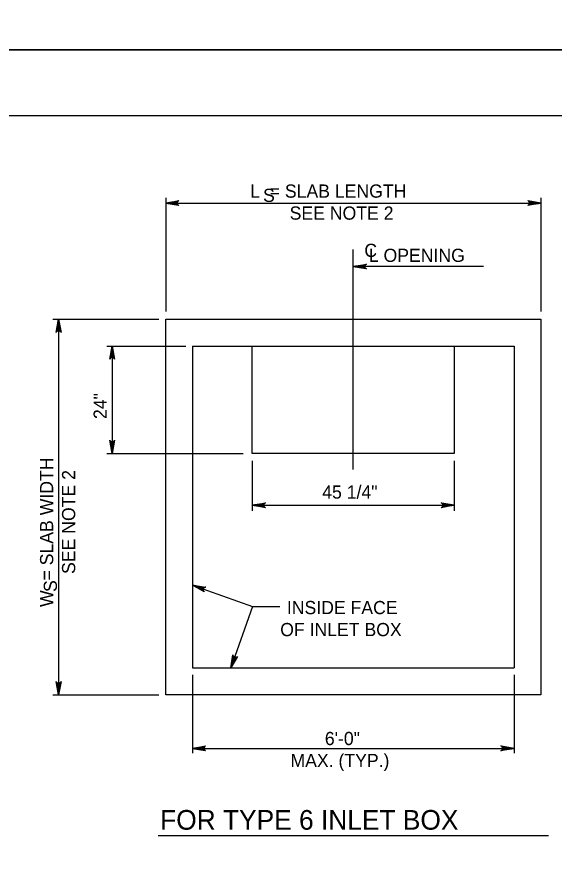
# Model space of a CAD drawing. Extents: x -6420 to 49575, y -4552 to 11624.
# Drawn here: x -5351 to -4949, y 9073 to 9700 of the extents above; entities that cross this region are included whole.
import ezdxf

# ---------------------------------------------------------------- set-up
doc = ezdxf.new("R2010")
doc.units = 0
doc.layers.add('1', color=7, linetype='Continuous')
doc.layers.add('PLT-BNDY', color=7, linetype='Continuous')

msp = doc.modelspace()

# ---------------------------------------------------------------- linework, layer by layer
at = {"layer": '1'}
for p, q in [((-5239.43, 9564.78), (-5239.43, 9479.86)), ((-4959.43, 9564.78), (-4959.43, 9479.86)), ((-5239.43, 9560.79), (-4959.43, 9560.79)), ((-5099.43, 9362.17), (-5099.43, 9526.19)), ((-5002.34, 9513.5), (-5099.43, 9513.5)), ((-5323.67, 9474.12), (-5244.69, 9474.12)), ((-5319.43, 9474.12), (-5319.43, 9194.12)), ((-5283.43, 9454.12), (-5224.45, 9454.12)), ((-5279.43, 9454.12), (-5279.43, 9374.12)), ((-5219.43, 9454.12), (-5219.43, 9214.12)), ((-5219.43, 9454.12), (-4979.43, 9454.12)), ((-5174.84, 9454.12), (-5024.01, 9454.12)), ((-5174.84, 9374.12), (-5174.84, 9454.12)), ((-5024.01, 9454.12), (-5024.01, 9374.12)), ((-4979.43, 9454.12), (-4979.43, 9214.12)), ((-5283.43, 9374.12), (-5181.53, 9374.12)), ((-5024.01, 9374.12), (-5174.84, 9374.12)), ((-5174.84, 9368.54), (-5174.84, 9331.24)), ((-5024.01, 9368.54), (-5024.01, 9331.24)), ((-5174.84, 9335.45), (-5024.01, 9335.45)), ((-5219.43, 9275.87), (-5174.71, 9259.98)), ((-5174.71, 9259.98), (-5190.87, 9214.12)), ((-5174.71, 9259.98), (-5154.27, 9259.98)), ((-5219.43, 9214.12), (-4979.43, 9214.12)), ((-5219.43, 9209), (-5219.43, 9150.51)), ((-4979.43, 9209), (-4979.43, 9150.51)), ((-5323.67, 9194.12), (-5244.69, 9194.12)), ((-5219.43, 9154.12), (-4979.43, 9154.12)), ((-5245.19, 9089.22), (-4953.81, 9089.22))]:
    msp.add_line(p, q, dxfattribs=at)
for points in [[(-3713.67, 7775.47), (-3713.67, 9625.87), (-6292.41, 9625.87), (-6292.41, 7775.47), (-3713.67, 7775.47), (-3713.67, 7861.95), (-4369.84, 7861.95), (-4369.84, 8074.15), (-3713.67, 8074.15), (-3713.67, 8169.17), (-4369.84, 8169.17), (-4369.84, 7775.47), (-4111.31, 7775.47), (-4111.31, 7861.95), (-4111.31, 7775.47), (-3858.68, 7775.47), (-3858.68, 7861.95), (-3858.68, 7821.54), (-3713.67, 7821.54)], [(-5239.43, 9560.79), (-5229.64, 9562.63), (-5230.02, 9562.37), (-5230.4, 9562.1), (-5230.59, 9561.78), (-5230.78, 9561.45), (-5230.84, 9561.12), (-5230.9, 9560.79), (-5230.84, 9560.46), (-5230.78, 9560.14), (-5230.59, 9559.81), (-5230.4, 9559.48), (-5230.02, 9559.22), (-5229.64, 9558.96), (-5239.43, 9560.79), (-5230.02, 9559.22), (-5230.4, 9559.48), (-5239.43, 9560.79), (-5230.59, 9559.81), (-5230.78, 9560.14), (-5239.43, 9560.79), (-5230.84, 9560.46), (-5230.9, 9560.79), (-5239.43, 9560.79), (-5230.84, 9561.12), (-5230.78, 9561.45), (-5239.43, 9560.79), (-5230.59, 9561.78), (-5230.4, 9562.1), (-5239.43, 9560.79), (-5230.02, 9562.37)], [(-4959.43, 9560.79), (-4969.21, 9558.96), (-4968.84, 9559.22), (-4968.46, 9559.48), (-4968.26, 9559.81), (-4968.07, 9560.14), (-4968.01, 9560.46), (-4967.96, 9560.79), (-4968.01, 9561.12), (-4968.07, 9561.45), (-4968.26, 9561.78), (-4968.46, 9562.1), (-4968.84, 9562.37), (-4969.21, 9562.63), (-4959.43, 9560.79), (-4968.84, 9562.37), (-4968.46, 9562.1), (-4959.43, 9560.79), (-4968.26, 9561.78), (-4968.07, 9561.45), (-4959.43, 9560.79), (-4968.01, 9561.12), (-4967.96, 9560.79), (-4959.43, 9560.79), (-4968.01, 9560.46), (-4968.07, 9560.14), (-4959.43, 9560.79), (-4968.26, 9559.81), (-4968.46, 9559.48), (-4959.43, 9560.79), (-4968.84, 9559.22)], [(-5099.43, 9513.5), (-5089.64, 9515.33), (-5090.02, 9515.07), (-5090.4, 9514.81), (-5090.59, 9514.48), (-5090.78, 9514.16), (-5090.84, 9513.83), (-5090.9, 9513.5), (-5090.84, 9513.17), (-5090.78, 9512.84), (-5090.59, 9512.52), (-5090.4, 9512.19), (-5090.02, 9511.93), (-5089.64, 9511.66), (-5099.43, 9513.5), (-5090.02, 9511.93), (-5090.4, 9512.19), (-5099.43, 9513.5), (-5090.59, 9512.52), (-5090.78, 9512.84), (-5099.43, 9513.5), (-5090.84, 9513.17), (-5090.9, 9513.5), (-5099.43, 9513.5), (-5090.84, 9513.83), (-5090.78, 9514.16), (-5099.43, 9513.5), (-5090.59, 9514.48), (-5090.4, 9514.81), (-5099.43, 9513.5), (-5090.02, 9515.07)], [(-5319.43, 9474.12), (-5317.59, 9464.34), (-5317.85, 9464.72), (-5318.12, 9465.09), (-5318.44, 9465.29), (-5318.77, 9465.48), (-5319.1, 9465.54), (-5319.43, 9465.59), (-5319.76, 9465.54), (-5320.08, 9465.48), (-5320.41, 9465.29), (-5320.74, 9465.09), (-5321, 9464.72), (-5321.26, 9464.34), (-5319.43, 9474.12), (-5321, 9464.72), (-5320.74, 9465.09), (-5319.43, 9474.12), (-5320.41, 9465.29), (-5320.08, 9465.48), (-5319.43, 9474.12), (-5319.76, 9465.54), (-5319.43, 9465.59), (-5319.43, 9474.12), (-5319.1, 9465.54), (-5318.77, 9465.48), (-5319.43, 9474.12), (-5318.44, 9465.29), (-5318.12, 9465.09), (-5319.43, 9474.12), (-5317.85, 9464.72)], [(-5279.43, 9454.12), (-5277.59, 9444.34), (-5277.85, 9444.72), (-5278.12, 9445.09), (-5278.44, 9445.29), (-5278.77, 9445.48), (-5279.1, 9445.54), (-5279.43, 9445.59), (-5279.76, 9445.54), (-5280.08, 9445.48), (-5280.41, 9445.29), (-5280.74, 9445.09), (-5281, 9444.72), (-5281.26, 9444.34), (-5279.43, 9454.12), (-5281, 9444.72), (-5280.74, 9445.09), (-5279.43, 9454.12), (-5280.41, 9445.29), (-5280.08, 9445.48), (-5279.43, 9454.12), (-5279.76, 9445.54), (-5279.43, 9445.59), (-5279.43, 9454.12), (-5279.1, 9445.54), (-5278.77, 9445.48), (-5279.43, 9454.12), (-5278.44, 9445.29), (-5278.12, 9445.09), (-5279.43, 9454.12), (-5277.85, 9444.72)], [(-5279.43, 9374.12), (-5281.26, 9383.91), (-5281, 9383.53), (-5280.74, 9383.16), (-5280.41, 9382.96), (-5280.08, 9382.77), (-5279.76, 9382.71), (-5279.43, 9382.65), (-5279.1, 9382.71), (-5278.77, 9382.77), (-5278.44, 9382.96), (-5278.12, 9383.16), (-5277.85, 9383.53), (-5277.59, 9383.91), (-5279.43, 9374.12), (-5277.85, 9383.53), (-5278.12, 9383.16), (-5279.43, 9374.12), (-5278.44, 9382.96), (-5278.77, 9382.77), (-5279.43, 9374.12), (-5279.1, 9382.71), (-5279.43, 9382.65), (-5279.43, 9374.12), (-5279.76, 9382.71), (-5280.08, 9382.77), (-5279.43, 9374.12), (-5280.41, 9382.96), (-5280.74, 9383.16), (-5279.43, 9374.12), (-5281, 9383.53)], [(-5174.84, 9335.45), (-5165.06, 9337.28), (-5165.44, 9337.02), (-5165.81, 9336.76), (-5166.01, 9336.43), (-5166.2, 9336.1), (-5166.26, 9335.78), (-5166.31, 9335.45), (-5166.26, 9335.12), (-5166.2, 9334.79), (-5166.01, 9334.46), (-5165.81, 9334.14), (-5165.44, 9333.87), (-5165.06, 9333.61), (-5174.84, 9335.45), (-5165.44, 9333.87), (-5165.81, 9334.14), (-5174.84, 9335.45), (-5166.01, 9334.46), (-5166.2, 9334.79), (-5174.84, 9335.45), (-5166.26, 9335.12), (-5166.31, 9335.45), (-5174.84, 9335.45), (-5166.26, 9335.78), (-5166.2, 9336.1), (-5174.84, 9335.45), (-5166.01, 9336.43), (-5165.81, 9336.76), (-5174.84, 9335.45), (-5165.44, 9337.02)], [(-5024.01, 9335.45), (-5033.8, 9333.61), (-5033.42, 9333.87), (-5033.04, 9334.14), (-5032.85, 9334.46), (-5032.65, 9334.79), (-5032.6, 9335.12), (-5032.54, 9335.45), (-5032.6, 9335.78), (-5032.65, 9336.1), (-5032.85, 9336.43), (-5033.04, 9336.76), (-5033.42, 9337.02), (-5033.8, 9337.28), (-5024.01, 9335.45), (-5033.42, 9337.02), (-5033.04, 9336.76), (-5024.01, 9335.45), (-5032.85, 9336.43), (-5032.65, 9336.1), (-5024.01, 9335.45), (-5032.6, 9335.78), (-5032.54, 9335.45), (-5024.01, 9335.45), (-5032.6, 9335.12), (-5032.65, 9334.79), (-5024.01, 9335.45), (-5032.85, 9334.46), (-5033.04, 9334.14), (-5024.01, 9335.45), (-5033.42, 9333.87)], [(-5219.43, 9275.87), (-5209.59, 9274.32), (-5210.04, 9274.2), (-5210.48, 9274.08), (-5210.77, 9273.84), (-5211.06, 9273.59), (-5211.23, 9273.3), (-5211.39, 9273.01), (-5211.45, 9272.68), (-5211.5, 9272.36), (-5211.43, 9271.98), (-5211.36, 9271.61), (-5211.09, 9271.24), (-5210.82, 9270.86), (-5219.43, 9275.87), (-5211.09, 9271.24), (-5211.36, 9271.61), (-5219.43, 9275.87), (-5211.43, 9271.98), (-5211.5, 9272.36), (-5219.43, 9275.87), (-5211.45, 9272.68), (-5211.39, 9273.01), (-5219.43, 9275.87), (-5211.23, 9273.3), (-5211.06, 9273.59), (-5219.43, 9275.87), (-5210.77, 9273.84), (-5210.48, 9274.08), (-5219.43, 9275.87), (-5210.04, 9274.2)], [(-5190.87, 9214.12), (-5189.35, 9223.96), (-5189.23, 9223.52), (-5189.11, 9223.08), (-5188.86, 9222.79), (-5188.62, 9222.49), (-5188.33, 9222.33), (-5188.04, 9222.17), (-5187.71, 9222.11), (-5187.38, 9222.06), (-5187.01, 9222.13), (-5186.63, 9222.21), (-5186.26, 9222.48), (-5185.89, 9222.74), (-5190.87, 9214.12), (-5186.26, 9222.48), (-5186.63, 9222.21), (-5190.87, 9214.12), (-5187.01, 9222.13), (-5187.38, 9222.06), (-5190.87, 9214.12), (-5187.71, 9222.11), (-5188.04, 9222.17), (-5190.87, 9214.12), (-5188.33, 9222.33), (-5188.62, 9222.49), (-5190.87, 9214.12), (-5188.86, 9222.79), (-5189.11, 9223.08), (-5190.87, 9214.12), (-5189.23, 9223.52)], [(-5319.43, 9194.12), (-5321.26, 9203.91), (-5321, 9203.53), (-5320.74, 9203.16), (-5320.41, 9202.96), (-5320.08, 9202.77), (-5319.76, 9202.71), (-5319.43, 9202.65), (-5319.1, 9202.71), (-5318.77, 9202.77), (-5318.44, 9202.96), (-5318.12, 9203.16), (-5317.85, 9203.53), (-5317.59, 9203.91), (-5319.43, 9194.12), (-5317.85, 9203.53), (-5318.12, 9203.16), (-5319.43, 9194.12), (-5318.44, 9202.96), (-5318.77, 9202.77), (-5319.43, 9194.12), (-5319.1, 9202.71), (-5319.43, 9202.65), (-5319.43, 9194.12), (-5319.76, 9202.71), (-5320.08, 9202.77), (-5319.43, 9194.12), (-5320.41, 9202.96), (-5320.74, 9203.16), (-5319.43, 9194.12), (-5321, 9203.53)], [(-5219.43, 9154.12), (-5209.64, 9155.96), (-5210.02, 9155.7), (-5210.4, 9155.44), (-5210.59, 9155.11), (-5210.78, 9154.78), (-5210.84, 9154.45), (-5210.9, 9154.12), (-5210.84, 9153.8), (-5210.78, 9153.47), (-5210.59, 9153.14), (-5210.4, 9152.81), (-5210.02, 9152.55), (-5209.64, 9152.29), (-5219.43, 9154.12), (-5210.02, 9152.55), (-5210.4, 9152.81), (-5219.43, 9154.12), (-5210.59, 9153.14), (-5210.78, 9153.47), (-5219.43, 9154.12), (-5210.84, 9153.8), (-5210.9, 9154.12), (-5219.43, 9154.12), (-5210.84, 9154.45), (-5210.78, 9154.78), (-5219.43, 9154.12), (-5210.59, 9155.11), (-5210.4, 9155.44), (-5219.43, 9154.12), (-5210.02, 9155.7)], [(-4979.43, 9154.12), (-4989.21, 9152.29), (-4988.84, 9152.55), (-4988.46, 9152.81), (-4988.26, 9153.14), (-4988.07, 9153.47), (-4988.01, 9153.8), (-4987.96, 9154.12), (-4988.01, 9154.45), (-4988.07, 9154.78), (-4988.26, 9155.11), (-4988.46, 9155.44), (-4988.84, 9155.7), (-4989.21, 9155.96), (-4979.43, 9154.12), (-4988.84, 9155.7), (-4988.46, 9155.44), (-4979.43, 9154.12), (-4988.26, 9155.11), (-4988.07, 9154.78), (-4979.43, 9154.12), (-4988.01, 9154.45), (-4987.96, 9154.12), (-4979.43, 9154.12), (-4988.01, 9153.8), (-4988.07, 9153.47), (-4979.43, 9154.12), (-4988.26, 9153.14), (-4988.46, 9152.81), (-4979.43, 9154.12), (-4988.84, 9152.55)]]:
    msp.add_lwpolyline(points, dxfattribs=at)
msp.add_lwpolyline([(-5239.43, 9474.12), (-4959.43, 9474.12), (-4959.43, 9194.12), (-5239.43, 9194.12)], close=True, dxfattribs=at)
at = {"layer": 'PLT-BNDY'}
for points in [[(-6420.37, 11623.9), (-3661.18, 11623.9), (-3661.18, 9675.08), (-6420.37, 9675.08)], [(-6420.37, 9675.08), (-3661.18, 9675.08), (-3661.18, 7726.26), (-6420.37, 7726.26)]]:
    msp.add_lwpolyline(points, close=True, dxfattribs=at)

# ---------------------------------------------------------------- texts
at = {"layer": '1'}
for s, height, p in [('L  = SLAB LENGTH', 9.8425, (-5176.46, 9564.79)), ('S', 9.84, (-5166.79, 9561.63)), ('SEE NOTE 2', 9.843, (-5146.93, 9548.38)), ('C', 9.84, (-5091.17, 9520.59)), ('L OPENING', 9.843, (-5087.83, 9516.88)), ('45 1/4"', 9.843, (-5122.61, 9340.34)), ('INSIDE FACE', 9.8425, (-5148.99, 9254.19)), ('OF INLET BOX', 9.8425, (-5153.98, 9237.79)), ('6\'-0"', 9.843, (-5120.66, 9156.55)), ('MAX. (TYP.)', 9.8425, (-5146.31, 9140.14)), ('FOR TYPE 6 INLET BOX', 14.6898, (-5243.61, 9093.44))]:
    msp.add_text(s, height=height, dxfattribs=at).set_placement(p)
for s, height, p in [('24"', 9.843, (-5283.46, 9399.72)), ('W  = SLAB WIDTH', 9.8425, (-5323.43, 9259.54)), ('SEE NOTE 2', 9.843, (-5307.02, 9284.15)), ('S', 9.84, (-5320.64, 9270.7))]:
    msp.add_text(s, height=height, rotation=90, dxfattribs=at).set_placement(p)

doc.saveas('drawing.dxf')
